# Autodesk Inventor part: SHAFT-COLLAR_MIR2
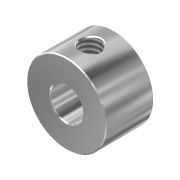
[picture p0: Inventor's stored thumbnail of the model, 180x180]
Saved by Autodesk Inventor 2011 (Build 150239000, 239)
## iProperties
Created: 2008-03
Part Number: SHAFT-COLLAR_MIR2
Document SubType Name: Modeling
Density: 1 g/cm^3
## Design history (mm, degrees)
derived "SHAFT-COLLAR.ipt"
  sketch "Sketch1"
    geometry: C1 r 5.499 at (7.091, -3.091) reference
  sketch "Sketch2"
    geometry: C1 r 5.499 at (0, 0) reference
  sketch "Sketch3"
    geometry: L1 (5.499, 0)-(-5.499, 0) reference; L2 (5.499, 0)-(5.499, -6.604) reference; 3 further points
  workplane "Work Plane1"
body "Solid1"
tag "TaggingFeature2"
feature "DerivedBody::SHAFT-COLLAR.ipt" dims "d0" = 10
